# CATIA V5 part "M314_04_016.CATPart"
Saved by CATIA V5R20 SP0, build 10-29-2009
Part number: M314_04_016
Source: Unknown
Property "ARTICLENO": "M314-04-016"
Property "B": "45.000"
Property "BOMINFO": "M314-04-016"
Property "CODE": "M314-04-016"
Property "D": "10.000"
Property "FINALFORCE": "196.1 (20)"
Property "INITIALFORCE": "39.2 (4)"
Property "K": "15.000"
Property "L": "60.000"
Property "LINA": "M314-04-016"
Property "M": "M24x3.0"
Property "NB": "M314-04-016"
Property "NBSYN": "$CODE."
Property "NN": "M314-04"
Property "NT": "Spring Plunger"
Property "SUPPLIER": "CF"
Property "SW": "8.000"
Bounding box of the stored display mesh (mm): x -11.878 to 11.878, y 0 to 75, z -12 to 12
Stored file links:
  C:\Users\Utente\Desktop\3D files M314\M314_04_016.CATPart
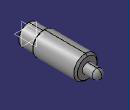
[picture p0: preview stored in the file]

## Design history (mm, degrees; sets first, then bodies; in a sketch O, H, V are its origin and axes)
Body1 "Geometry.1" (main body)
  Solid1 "M314_04_016.catpart": solid without history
